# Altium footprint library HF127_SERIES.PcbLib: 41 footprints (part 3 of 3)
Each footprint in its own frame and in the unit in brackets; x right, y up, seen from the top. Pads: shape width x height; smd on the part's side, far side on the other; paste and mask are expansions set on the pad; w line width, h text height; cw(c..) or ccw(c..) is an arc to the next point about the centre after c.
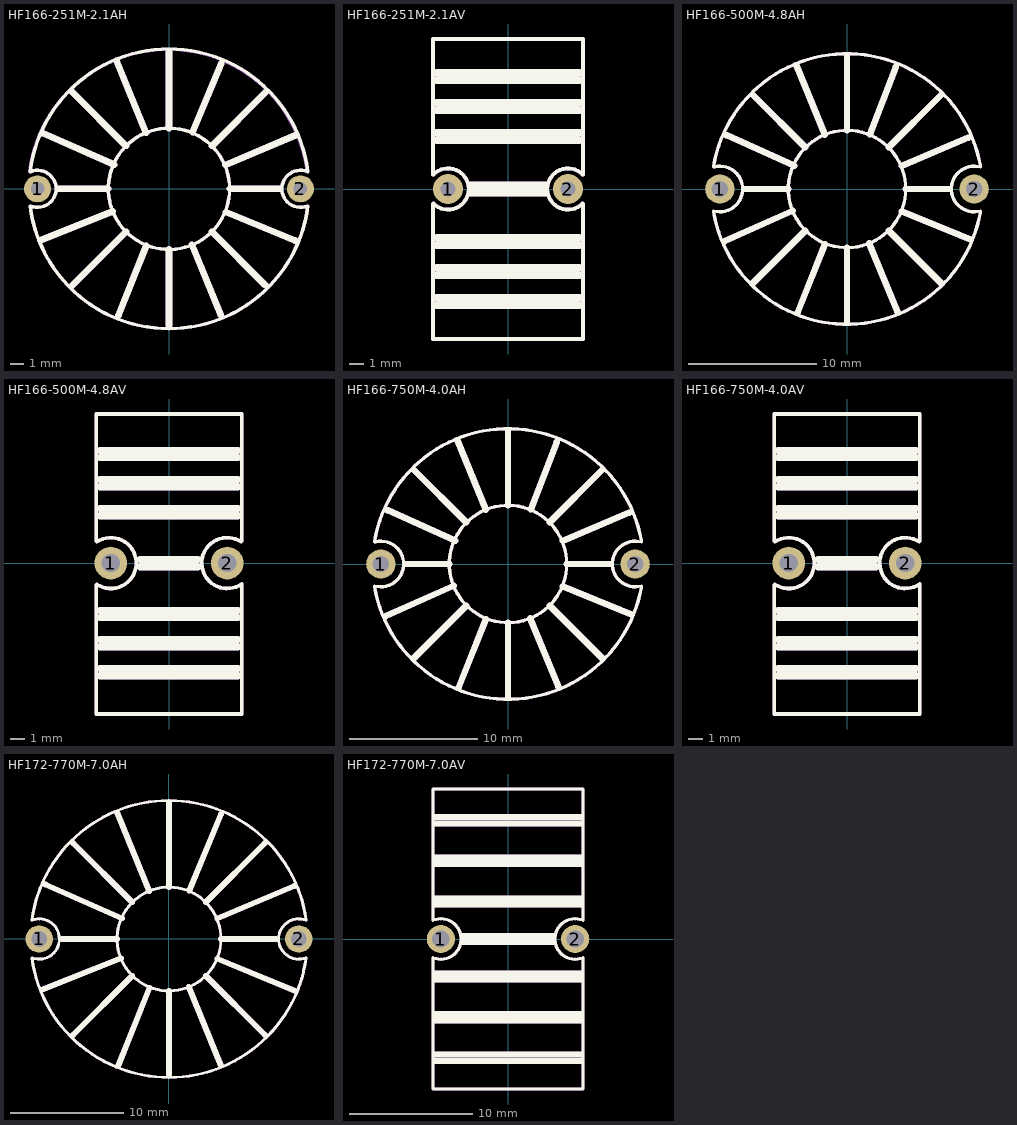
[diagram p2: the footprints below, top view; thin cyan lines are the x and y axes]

## HF166-251M-2.1AH [mil]
pads (2):
  round 80 hole 40: 1(-390,0) 2(390,0)
Top Overlay:
  circle w10: c0,0 r180
  lines w10: -411.83,-51.16 ccw(c0,0) 411.83,-51.16 ; -411.83,51.16 cw(c0,0) 411.85,51 ; -410.57,-51.01 ccw(c-390,0) -410.57,51.01 ; 410.57,-51.01 cw(c390,0) 410.88,50.88
  lines w19.68: -381.03,-152.41 -166.38,-66.55 ; -374.91,165.21 -162.15,71.46 ; -330,0 -180,0 ; -290,290 -127.5,127.5 ; -287.5,-287.5 -127.5,-127.5 ; -155.63,379.74 -67.96,165.83 ; -150,-375 -67.59,-168.97 ; 0,-405 0,-180 ; 0,180 0,405 ; 67.96,-165.83 153.88,-375.46 ; 69.97,167.93 155.33,372.78 ; 127.5,-127.5 285,-285 ; 127.5,127.5 285,285 ; 167.47,70.96 375.4,159.07 ; 168.36,-69 373.71,-153.16 ; 180,0 330,0
Mechanical 29:
  circle w10: c0,0 r180
  lines w10: -413.69,50.16 cw(c-1.85,-1) 410,50 ; -411.83,-51.16 ccw(c0,0) 411.83,-51.16 ; -410.57,-51.01 ccw(c-390,0) -410.57,51.01 ; 410.57,-51.01 cw(c390,0) 410.88,50.88
  lines w19.68: -381.03,-152.41 -166.38,-66.55 ; -374.91,165.21 -162.15,71.46 ; -330,0 -180,0 ; -290,290 -127.5,127.5 ; -287.5,-287.5 -127.5,-127.5 ; -155.63,379.74 -67.96,165.83 ; -150,-375 -67.59,-168.97 ; 0,-405 0,-180 ; 0,180 0,405 ; 67.96,-165.83 153.88,-375.46 ; 69.97,167.93 155.33,372.78 ; 127.5,-127.5 285,-285 ; 127.5,127.5 285,285 ; 167.47,70.96 375.4,159.07 ; 168.36,-69 373.71,-153.16 ; 180,0 330,0
  text "'.Designator'" at -1750,-64.85 h400

## HF166-251M-2.1AV [mil]
pads (2):
  round 80 hole 40: 1(-160,0) 2(160,0)
Top Overlay:
  lines w10: -200,-39 -200,-400 200,-400 200,-39 ; -200,39 -200,400 200,400 200,39 ; -198.89,-38.89 ccw(c-160,0) -198.89,38.89 ; 198.89,-38.89 cw(c160,0) 198.89,38.89
  lines w19.68: -190,-310 190,-310 ; -190,-290 190,-290 ; -190,-230 190,-230 ; -190,-210 190,-210 ; -190,-150 190,-150 ; -190,-130 190,-130 ; -190,130 190,130 ; -190,150 190,150 ; -190,210 190,210 ; -190,230 190,230 ; -190,290 190,290 ; -190,310 190,310 ; -100,-10 100,-10 ; -100,10 100,10
Mechanical 29:
  lines w10: -200,-39 -200,-400 200,-400 200,-39 ; -200,39 -200,400 200,400 200,39 ; -198.89,-38.89 ccw(c-160,0) -198.89,38.89 ; 198.89,-38.89 cw(c160,0) 198.89,38.89
  lines w19.68: -190,-310 190,-310 ; -190,-290 190,-290 ; -190,-230 190,-230 ; -190,-210 190,-210 ; -190,-150 190,-150 ; -190,-130 190,-130 ; -190,130 190,130 ; -190,150 190,150 ; -190,210 190,210 ; -190,230 190,230 ; -190,290 190,290 ; -190,310 190,310 ; -100,-10 100,-10 ; -100,10 100,10
  text "'.Designator'" at -1750,-64.85 h400

## HF166-500M-4.8AH [mil]
pads (2):
  round 90 hole 50: 1(-390,0) 2(390,0)
Top Overlay:
  circle w10: c0,0 r180
  lines w10: -409.5,-67.32 ccw(c0,0) 409.08,-69.84 ; -409.48,67.48 cw(c0,0) 409.08,69.84 ; -409.23,-67.31 ccw(c-390,0) -405.74,68.21 ; 409.23,-67.31 cw(c390,0) 409.23,67.31
  lines w19.68: -375,-160 -166.38,-66.55 ; -370,165 -162.15,71.46 ; -315,0 -180,0 ; -290,-290 -127.5,-127.5 ; -287.5,287.5 -127.5,127.5 ; -155.32,378.97 -67.96,165.83 ; -151.03,-377.59 -67.59,-168.97 ; 0,-410 0,-180 ; 0,180 0,410 ; 67.96,-165.83 154.19,-376.23 ; 69.97,167.93 150,375 ; 127.5,-127.5 290,-290 ; 127.5,127.5 287.5,287.5 ; 167.47,70.96 371.8,157.54 ; 168.36,-69 378.97,-155.32 ; 180,0 315,0
Mechanical 29:
  circle w10: c0,0 r180
  lines w10: -409.5,-67.32 ccw(c0,0) 409.08,-69.84 ; -409.48,67.48 cw(c0,0) 409.08,69.84 ; -409.23,-67.31 ccw(c-390,0) -405.74,68.21 ; 409.23,-67.31 cw(c390,0) 409.23,67.31
  lines w19.68: -375,-160 -166.38,-66.55 ; -370,165 -162.15,71.46 ; -315,0 -180,0 ; -290,-290 -127.5,-127.5 ; -287.5,287.5 -127.5,127.5 ; -155.32,378.97 -67.96,165.83 ; -151.03,-377.59 -67.59,-168.97 ; 0,-410 0,-180 ; 0,180 0,410 ; 67.96,-165.83 154.19,-376.23 ; 69.97,167.93 150,375 ; 127.5,-127.5 290,-290 ; 127.5,127.5 287.5,287.5 ; 167.47,70.96 371.8,157.54 ; 168.36,-69 378.97,-155.32 ; 180,0 315,0
  text "'.Designator'" at -1750,-64.85 h400

## HF166-500M-4.8AV [mil]
pads (2):
  round 90 hole 50: 1(-160,0) 2(160,0)
Top Overlay:
  lines w10: -200,-60 -200,-415 200,-415 ; -200,60 -200,410 200,410 200,60 ; -198.83,-58.24 ccw(c-160,0) -198.83,58.24 ; 198.83,58.24 ccw(c160,0) 200,-57.45 200,-410
  lines w19.68: -190,-310 190,-310 ; -190,-290 190,-290 ; -190,-230 190,-230 ; -190,-210 190,-210 ; -190,-150 190,-150 ; -190,-130 190,-130 ; -190,130 190,130 ; -190,150 190,150 ; -190,210 190,210 ; -190,230 190,230 ; -190,290 190,290 ; -190,310 190,310 ; -80,-10 80,-10 ; -80,10 80,10
Mechanical 29:
  lines w10: -200,-60 -200,-415 200,-415 ; -200,60 -200,410 200,410 200,60 ; -198.83,-58.24 ccw(c-160,0) -198.83,58.24 ; 198.83,58.24 ccw(c160,0) 200,-57.45 200,-410
  lines w19.68: -190,-310 190,-310 ; -190,-290 190,-290 ; -190,-230 190,-230 ; -190,-210 190,-210 ; -190,-150 190,-150 ; -190,-130 190,-130 ; -190,130 190,130 ; -190,150 190,150 ; -190,210 190,210 ; -190,230 190,230 ; -190,290 190,290 ; -190,310 190,310 ; -80,-10 80,-10 ; -80,10 80,10
  text "'.Designator'" at -1750,-64.85 h400

## HF166-750M-4.0AH [mil]
pads (2):
  round 90 hole 50: 1(-390,0) 2(390,0)
Top Overlay:
  circle w10: c0,0 r180
  lines w10: -409.5,-67.32 ccw(c0,0) 409.08,-69.84 ; -409.48,67.48 cw(c0,0) 409.08,69.84 ; -409.23,-67.31 ccw(c-390,0) -405.74,68.21 ; 409.23,-67.31 cw(c390,0) 409.23,67.31
  lines w19.68: -375,-160 -166.38,-66.55 ; -370,165 -162.15,71.46 ; -315,0 -180,0 ; -290,-290 -127.5,-127.5 ; -287.5,287.5 -127.5,127.5 ; -155.32,378.97 -67.96,165.83 ; -151.03,-377.59 -67.59,-168.97 ; 0,-410 0,-180 ; 0,180 0,410 ; 67.96,-165.83 154.19,-376.23 ; 69.97,167.93 150,375 ; 127.5,-127.5 290,-290 ; 127.5,127.5 287.5,287.5 ; 167.47,70.96 371.8,157.54 ; 168.36,-69 378.97,-155.32 ; 180,0 315,0
Mechanical 29:
  circle w10: c0,0 r180
  lines w10: -409.5,-67.32 ccw(c0,0) 409.08,-69.84 ; -409.48,67.48 cw(c0,0) 409.08,69.84 ; -409.23,-67.31 ccw(c-390,0) -405.74,68.21 ; 409.23,-67.31 cw(c390,0) 409.23,67.31
  lines w19.68: -375,-160 -166.38,-66.55 ; -370,165 -162.15,71.46 ; -315,0 -180,0 ; -290,-290 -127.5,-127.5 ; -287.5,287.5 -127.5,127.5 ; -155.32,378.97 -67.96,165.83 ; -151.03,-377.59 -67.59,-168.97 ; 0,-410 0,-180 ; 0,180 0,410 ; 67.96,-165.83 154.19,-376.23 ; 69.97,167.93 150,375 ; 127.5,-127.5 290,-290 ; 127.5,127.5 287.5,287.5 ; 167.47,70.96 371.8,157.54 ; 168.36,-69 378.97,-155.32 ; 180,0 315,0
  text "'.Designator'" at -1750,-64.85 h400

## HF166-750M-4.0AV [mil]
pads (2):
  round 90 hole 50: 1(-160,0) 2(160,0)
Top Overlay:
  lines w10: -200,-60 -200,-415 200,-415 ; -200,60 -200,410 200,410 200,60 ; -198.83,-58.24 ccw(c-160,0) -198.83,58.24 ; 198.83,58.24 ccw(c160,0) 200,-57.45 200,-410
  lines w19.68: -190,-310 190,-310 ; -190,-290 190,-290 ; -190,-230 190,-230 ; -190,-210 190,-210 ; -190,-150 190,-150 ; -190,-130 190,-130 ; -190,130 190,130 ; -190,150 190,150 ; -190,210 190,210 ; -190,230 190,230 ; -190,290 190,290 ; -190,310 190,310 ; -80,-10 80,-10 ; -80,10 80,10
Mechanical 29:
  lines w10: -200,-60 -200,-415 200,-415 ; -200,60 -200,410 200,410 200,60 ; -198.83,-58.24 ccw(c-160,0) -198.83,58.24 ; 198.83,58.24 ccw(c160,0) 200,-57.45 200,-410
  lines w19.68: -190,-310 190,-310 ; -190,-290 190,-290 ; -190,-230 190,-230 ; -190,-210 190,-210 ; -190,-150 190,-150 ; -190,-130 190,-130 ; -190,130 190,130 ; -190,150 190,150 ; -190,210 190,210 ; -190,230 190,230 ; -190,290 190,290 ; -190,310 190,310 ; -80,-10 80,-10 ; -80,10 80,10
  text "'.Designator'" at -1750,-64.85 h400

## HF172-770M-7.0AH [mil]
pads (2):
  round 95 hole 55: 1(-450,0) 2(450,0)
Top Overlay:
  circle w10: c0,0 r180
  lines w10: -475.41,-66.23 ccw(c0,0) 475.56,-65.17 cw(c450,0) 475.56,65.17 ccw(c0,0) -475.56,65.17 cw(c-450,0) -473.44,-65.96
  lines w19.68: -440.52,-176.21 -166.38,-66.55 ; -428.34,188.76 -162.15,71.46 ; -370,0 -180,0 ; -332.5,-332.5 -127.5,-127.5 ; -332.5,332.5 -127.5,127.5 ; -179.56,438.13 -67.96,165.83 ; -175.52,-438.79 -67.59,-168.97 ; 0,-470 0,-180 ; 0,180 0,475 ; 67.96,-165.83 179.56,-438.13 ; 69.97,167.93 180.33,432.78 ; 127.5,-127.5 332.5,-332.5 ; 127.5,127.5 332.5,332.5 ; 167.47,70.96 434.09,183.94 ; 168.36,-69 436.59,-178.93 ; 180,0 370,0
Mechanical 29:
  circle w10: c0,0 r180
  lines w10: -475.41,-66.23 ccw(c0,0) 475.56,-65.17 cw(c450,0) 475.56,65.17 ccw(c0,0) -475.56,65.17 cw(c-450,0) -473.44,-65.96
  lines w19.68: -440.52,-176.21 -166.38,-66.55 ; -428.34,188.76 -162.15,71.46 ; -370,0 -180,0 ; -332.5,-332.5 -127.5,-127.5 ; -332.5,332.5 -127.5,127.5 ; -179.56,438.13 -67.96,165.83 ; -175.52,-438.79 -67.59,-168.97 ; 0,-470 0,-180 ; 0,180 0,475 ; 67.96,-165.83 179.56,-438.13 ; 69.97,167.93 180.33,432.78 ; 127.5,-127.5 332.5,-332.5 ; 127.5,127.5 332.5,332.5 ; 167.47,70.96 434.09,183.94 ; 168.36,-69 436.59,-178.93 ; 180,0 370,0
  text "'.Designator'" at -1750,-64.85 h400

## HF172-770M-7.0AV [mil]
pads (2):
  round 90 hole 55: 1(-215,0) 2(215,0)
Top Overlay:
  lines w10: -240,-480 -240,-60 ccw(c-215,0) -240,60 -240,480 240,480 240,60 ccw(c215,0) 240,-60 240,-480 -240,-480
  lines w19.68: -235,-390 235,-390 ; -235,-370 235,-370 ; -235,-260 235,-260 ; -235,-240 235,-240 ; -235,-130 235,-130 ; -235,-110 235,-110 ; -235,110 235,110 ; -235,130 235,130 ; -235,240 235,240 ; -235,260 235,260 ; -235,370 235,370 ; -235,390 235,390 ; -145,-10 145,-10 ; -145,10 145,10
Mechanical 29:
  lines w10: -240,-480 -240,-60 ccw(c-215,0) -240,60 -240,480 240,480 240,60 ccw(c215,0) 240,-60 240,-480 -240,-480
  lines w19.68: -235,-390 235,-390 ; -235,-370 235,-370 ; -235,-260 235,-260 ; -235,-240 235,-240 ; -235,-130 235,-130 ; -235,-110 235,-110 ; -235,110 235,110 ; -235,130 235,130 ; -235,240 235,240 ; -235,260 235,260 ; -235,370 235,370 ; -235,390 235,390 ; -145,-10 145,-10 ; -145,10 145,10
  text "'.Designator'" at -1750,-64.85 h400

## PCBComponent_1 [mil]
